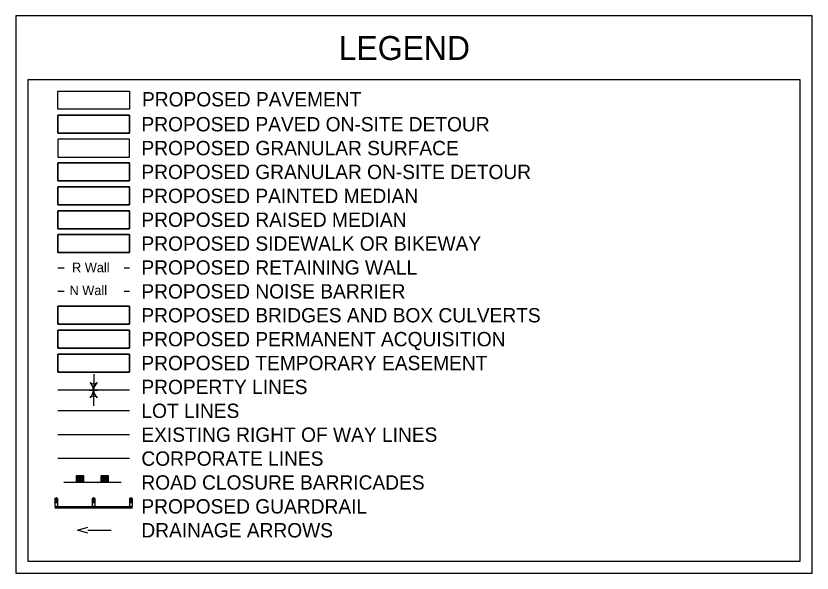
# Model space of a CAD drawing. Extents: x 4992991 to 4999031, y 3881203 to 3897170.
# Drawn here: x 4992991 to 4993991, y 3881279 to 3881979 of the extents above; entities that cross this region are included whole.
import ezdxf

# ---------------------------------------------------------------- set-up
doc = ezdxf.new("R2010")
doc.units = 0
doc.layers.add('dsnErosionControl', color=7, linetype='Continuous')
doc.layers.add('dsnProfileGradePropLine', color=7, linetype='Continuous')

msp = doc.modelspace()

# ---------------------------------------------------------------- linework, layer by layer
at = {"layer": 'dsnErosionControl'}
msp.add_line((4993134, 3881824.4), (4993044, 3881824.4), dxfattribs=at)
msp.add_lwpolyline([(4993044, 3881824.4), (4993044, 3881801.9), (4993134, 3881801.9), (4993134, 3881824.4)], dxfattribs=at)
at = {"layer": 'dsnProfileGradePropLine'}
for p, q in [((4993044, 3881791.6), (4993044, 3881771.9)), ((4993134, 3881771.9), (4993134, 3881794.4)), ((4993044, 3881771.9), (4993134, 3881771.9)), ((4993052.1, 3881662.4), (4993044, 3881662.4)), ((4993134, 3881662.4), (4993127.2, 3881662.4)), ((4993052.1, 3881633.1), (4993044, 3881633.1)), ((4993134, 3881633.1), (4993127.2, 3881633.1)), ((4993089, 3881529), (4993089, 3881509.2)), ((4993134, 3881509.2), (4993044, 3881509.2)), ((4993083.4, 3881509.2), (4993094.5, 3881509.2)), ((4993089, 3881489.3), (4993089, 3881509.2)), ((4993134, 3881483.2), (4993044, 3881483.2)), ((4993134, 3881453.2), (4993044, 3881453.2)), ((4993134, 3881423.2), (4993044, 3881423.2)), ((4993067.7, 3881401.4), (4993076.1, 3881401.4)), ((4993076.1, 3881400.9), (4993067.7, 3881400.9)), ((4993067.7, 3881400.5), (4993076.1, 3881400.5)), ((4993076.1, 3881400.1), (4993067.7, 3881400.1)), ((4993067.7, 3881399.7), (4993076.1, 3881399.7)), ((4993076.1, 3881399.1), (4993067.7, 3881399.1)), ((4993067.7, 3881398.8), (4993076.1, 3881398.8)), ((4993076.1, 3881398.1), (4993067.7, 3881398.1)), ((4993098.6, 3881401.4), (4993107, 3881401.4)), ((4993107, 3881400.9), (4993098.6, 3881400.9)), ((4993098.6, 3881400.5), (4993107, 3881400.5)), ((4993107, 3881400.1), (4993098.6, 3881400.1)), ((4993098.6, 3881399.7), (4993107, 3881399.7)), ((4993107, 3881399.1), (4993098.6, 3881399.1)), ((4993098.6, 3881398.8), (4993107, 3881398.8)), ((4993107, 3881398.1), (4993098.6, 3881398.1)), ((4993051.5, 3881393.5), (4993123.7, 3881393.5)), ((4993067.7, 3881397.6), (4993076.1, 3881397.6)), ((4993076.1, 3881397.1), (4993067.7, 3881397)), ((4993067.7, 3881396.7), (4993076.1, 3881396.7)), ((4993076.1, 3881396.3), (4993067.7, 3881396.3)), ((4993067.7, 3881395.8), (4993076.1, 3881395.8)), ((4993076.1, 3881395.5), (4993067.7, 3881395.5)), ((4993067.7, 3881395.2), (4993076.1, 3881395.2)), ((4993076.1, 3881394.8), (4993067.7, 3881394.8)), ((4993067.7, 3881394.4), (4993076.1, 3881394.4)), ((4993076.1, 3881394), (4993067.7, 3881394)), ((4993098.6, 3881397.6), (4993107, 3881397.6)), ((4993107, 3881397.1), (4993098.6, 3881397)), ((4993098.6, 3881396.7), (4993107, 3881396.7)), ((4993107, 3881396.3), (4993098.6, 3881396.3)), ((4993098.6, 3881395.8), (4993107, 3881395.8)), ((4993107, 3881395.5), (4993098.6, 3881395.5)), ((4993098.6, 3881395.2), (4993107, 3881395.2)), ((4993107, 3881394.8), (4993098.6, 3881394.8)), ((4993098.6, 3881394.4), (4993107, 3881394.4)), ((4993107, 3881394), (4993098.6, 3881394)), ((4993044, 3881368.2), (4993040.2, 3881373.2)), ((4993040.2, 3881368.2), (4993044, 3881373.2)), ((4993044, 3881373.2), (4993040.2, 3881373.2)), ((4993041.5, 3881373.2), (4993041.5, 3881373.3)), ((4993042.7, 3881373.3), (4993041.5, 3881373.3)), ((4993041.8, 3881373.3), (4993041.8, 3881373.6)), ((4993042.4, 3881373.6), (4993041.8, 3881373.6)), ((4993041.9, 3881373.3), (4993041.9, 3881373.6)), ((4993042, 3881373.6), (4993042, 3881373.8)), ((4993042.2, 3881373.8), (4993042, 3881373.8)), ((4993042.2, 3881373.6), (4993042.2, 3881373.8)), ((4993042.3, 3881373.3), (4993042.3, 3881373.6)), ((4993042.4, 3881373.3), (4993042.4, 3881373.6)), ((4993042.7, 3881373.2), (4993042.7, 3881373.3)), ((4993090.8, 3881368.2), (4993087.1, 3881373.2)), ((4993087.1, 3881368.2), (4993090.8, 3881373.2)), ((4993090.8, 3881373.2), (4993087.1, 3881373.2)), ((4993088.4, 3881373.2), (4993088.4, 3881373.3)), ((4993089.6, 3881373.3), (4993088.4, 3881373.3)), ((4993088.7, 3881373.3), (4993088.7, 3881373.6)), ((4993089.3, 3881373.6), (4993088.7, 3881373.6)), ((4993088.8, 3881373.3), (4993088.8, 3881373.6)), ((4993088.9, 3881373.6), (4993088.9, 3881373.8)), ((4993089, 3881373.8), (4993088.9, 3881373.8)), ((4993089, 3881373.6), (4993089, 3881373.8)), ((4993089.2, 3881373.3), (4993089.2, 3881373.6)), ((4993089.3, 3881373.3), (4993089.3, 3881373.6)), ((4993089.6, 3881373.2), (4993089.6, 3881373.3)), ((4993137.7, 3881368.2), (4993134, 3881373.2)), ((4993134, 3881368.2), (4993137.7, 3881373.2)), ((4993137.7, 3881373.2), (4993134, 3881373.2)), ((4993135.2, 3881373.2), (4993135.2, 3881373.3)), ((4993136.4, 3881373.3), (4993135.2, 3881373.3)), ((4993135.5, 3881373.3), (4993135.5, 3881373.6)), ((4993136.1, 3881373.6), (4993135.5, 3881373.6)), ((4993135.7, 3881373.3), (4993135.7, 3881373.6)), ((4993135.8, 3881373.6), (4993135.8, 3881373.8)), ((4993135.9, 3881373.8), (4993135.8, 3881373.8)), ((4993135.9, 3881373.6), (4993135.9, 3881373.8)), ((4993136, 3881373.3), (4993136, 3881373.6)), ((4993136.1, 3881373.3), (4993136.1, 3881373.6)), ((4993136.4, 3881373.2), (4993136.4, 3881373.3)), ((4993044, 3881363.2), (4993040.2, 3881363.2)), ((4993040.2, 3881361.2), (4993137.7, 3881361.2)), ((4993130.2, 3881361.2), (4993040.2, 3881361.2)), ((4993040.3, 3881363.2), (4993137.7, 3881363.2)), ((4993090.8, 3881363.2), (4993087.1, 3881363.2)), ((4993137.7, 3881363.2), (4993134, 3881363.2)), ((4993081.8, 3881333.2), (4993110.9, 3881333.2))]:
    msp.add_line(p, q, dxfattribs=at)
for points in [[(4993991.3, 3881279.4), (4993991.3, 3881979.1), (4992991.3, 3881979.1), (4992991.3, 3881279.4)], [(4993006.3, 3881294.2), (4993976.3, 3881294.2), (4993976.3, 3881898.6), (4993006.3, 3881898.6)], [(4993044, 3881884.4), (4993134, 3881884.4), (4993134, 3881861.9), (4993044, 3881861.9)], [(4993044, 3881854.4), (4993134, 3881854.4), (4993134, 3881831.9), (4993044, 3881831.9)], [(4993044, 3881771.9), (4993134, 3881771.9), (4993134, 3881794.4), (4993044, 3881794.4)], [(4993044, 3881794.4), (4993134, 3881794.4), (4993134, 3881771.9), (4993044, 3881771.9)], [(4993044, 3881741.9), (4993134, 3881741.9), (4993134, 3881764.4), (4993044, 3881764.4)], [(4993044, 3881764.3), (4993134, 3881764.3), (4993134, 3881741.9), (4993044, 3881741.9)], [(4993044, 3881711.9), (4993134, 3881711.9), (4993134, 3881734.4), (4993044, 3881734.4)], [(4993044, 3881734.4), (4993134, 3881734.4), (4993134, 3881711.9), (4993044, 3881711.9)], [(4993044, 3881681.9), (4993134, 3881681.9), (4993134, 3881704.4), (4993044, 3881704.4)], [(4993044, 3881704.4), (4993134, 3881704.4), (4993134, 3881681.9), (4993044, 3881681.9)], [(4993044, 3881591.9), (4993134, 3881591.9), (4993134, 3881614.4), (4993044, 3881614.4)], [(4993044, 3881614.4), (4993134, 3881614.4), (4993134, 3881591.9), (4993044, 3881591.9)], [(4993044, 3881584.4), (4993134, 3881584.4), (4993134, 3881561.9), (4993044, 3881561.9)], [(4993044, 3881561.9), (4993134, 3881561.9), (4993134, 3881584.4), (4993044, 3881584.4)], [(4993044, 3881554.4), (4993134, 3881554.4), (4993134, 3881531.9), (4993044, 3881531.9)], [(4993044, 3881531.9), (4993134, 3881531.9), (4993134, 3881554.4), (4993044, 3881554.4)], [(4993076.1, 3881393.5), (4993067.6, 3881393.5), (4993067.6, 3881401.9), (4993076.1, 3881401.9)], [(4993107, 3881393.5), (4993098.6, 3881393.5), (4993098.6, 3881401.9), (4993107, 3881401.9)], [(4993040.2, 3881368.2), (4993044, 3881368.2), (4993044, 3881373.2), (4993040.2, 3881373.2)], [(4993040.2, 3881363.2), (4993044, 3881363.2), (4993044, 3881368.2), (4993040.2, 3881368.2)], [(4993087.1, 3881368.2), (4993090.8, 3881368.2), (4993090.8, 3881373.2), (4993087.1, 3881373.2)], [(4993087.1, 3881363.2), (4993090.8, 3881363.2), (4993090.8, 3881368.2), (4993087.1, 3881368.2)], [(4993134, 3881368.2), (4993137.7, 3881368.2), (4993137.7, 3881373.2), (4993134, 3881373.2)], [(4993134, 3881363.2), (4993137.7, 3881363.2), (4993137.7, 3881368.2), (4993134, 3881368.2)]]:
    msp.add_lwpolyline(points, close=True, dxfattribs=at)
for points in [[(4993044, 3881831.9), (4993134, 3881831.9), (4993134, 3881854.4)], [(4993134, 3881854.4), (4993044, 3881854.4), (4993044, 3881831.9)], [(4993134, 3881794.4), (4993044, 3881794.4), (4993044, 3881791.6)], [(4993134, 3881764.3), (4993044, 3881764.3), (4993044, 3881741.9)], [(4993044, 3881741.9), (4993134, 3881741.9), (4993134, 3881764.3)], [(4993081.8, 3881329.4), (4993068.5, 3881333.2), (4993081.8, 3881337)]]:
    msp.add_lwpolyline(points, dxfattribs=at)
for centre, radius, start, end in [((4993089, 3881523.7), 6.69, 228.4601, 311.5399), ((4993074.6, 3881508.3), 14.4, 3.6281, 46.3846), ((4993103.3, 3881508.3), 14.4, 133.6154, 176.3719), ((4993074.6, 3881510.1), 14.4, 313.6154, 356.3719), ((4993103.3, 3881510.1), 14.4, 183.6281, 226.3846), ((4993089, 3881494.7), 6.69, 48.4601, 131.5399)]:
    msp.add_arc(centre, radius, start, end, dxfattribs=at)

# ---------------------------------------------------------------- texts
for s, height, p in [('LEGEND', 30, (4993396.7, 3881923.8)), ('PROPOSED PAVEMENT', 18, (4993149.7, 3881865.4)), ('PROPOSED PAVED ON-SITE DETOUR', 18, (4993149, 3881834.1)), ('PROPOSED GRANULAR SURFACE', 18, (4993149, 3881804.1)), ('PROPOSED GRANULAR ON-SITE DETOUR', 18, (4993148.9, 3881774.2)), ('PROPOSED PAINTED MEDIAN', 18, (4993148.9, 3881744.1)), ('PROPOSED RAISED MEDIAN', 18, (4993148.9, 3881714.2)), ('PROPOSED SIDEWALK OR BIKEWAY', 18, (4993149, 3881684.2)), ('R Wall', 12, (4993061.8, 3881657.2)), ('PROPOSED RETAINING WALL', 18, (4993148.9, 3881654.2)), ('N Wall', 12, (4993058.6, 3881628.5)), ('PROPOSED NOISE BARRIER', 18, (4993148.9, 3881624.2)), ('PROPOSED BRIDGES AND BOX CULVERTS', 18, (4993148.9, 3881594.2)), ('PROPOSED PERMANENT ACQUISITION', 18, (4993148.9, 3881564.2)), ('PROPOSED TEMPORARY EASEMENT', 18, (4993148.9, 3881534.2)), ('PROPERTY LINES', 18, (4993148.9, 3881504.2)), ('LOT LINES', 18, (4993148.9, 3881474.2)), ('EXISTING RIGHT OF WAY LINES', 18, (4993148.9, 3881444.2)), ('CORPORATE LINES', 18, (4993148.9, 3881414.2)), ('ROAD CLOSURE BARRICADES', 18, (4993148.9, 3881384.2)), ('PROPOSED GUARDRAIL', 18, (4993148.9, 3881354.2)), ('DRAINAGE ARROWS', 18, (4993148.9, 3881324.2))]:
    msp.add_text(s, height=height, dxfattribs=at).set_placement(p)

doc.saveas('drawing.dxf')
